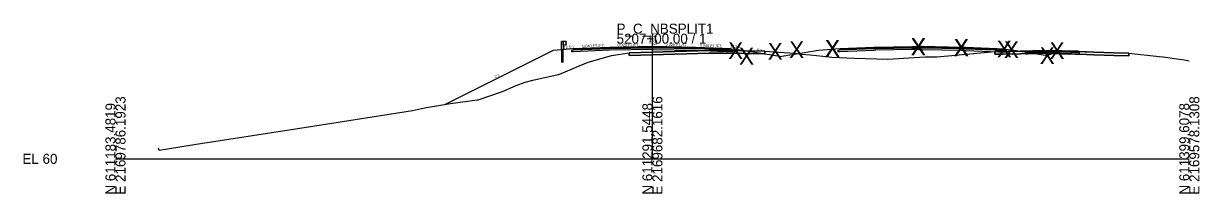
# Model space of a CAD drawing. Extents: x -26 to 1303, y -3010 to 12038.
# Drawn here: x 974.3 to 1302.8, y 4490.3 to 4537.8 of the extents above; entities that cross this region are included whole.
import ezdxf

# ---------------------------------------------------------------- set-up
doc = ezdxf.new("R2010")
doc.units = 0
for name, color, linetype in [('RD_GPK_XS_Cell', 7, 'Continuous'), ('RD_GPK_XS_Text_Node', 7, 'Continuous'), ('RD_PD_Final_TrvlWay', 7, 'Continuous'), ('RD_XS_Base', 7, 'Continuous'), ('RD_XS_ExGround', 7, 'Continuous'), ('RD_XS_ExPaveRet', 7, 'Continuous'), ('RD_XS_GR', 7, 'Continuous'), ('RD_XS_Greenside', 7, 'Continuous'), ('RD_XS_Pave', 7, 'Continuous'), ('RD_XS_PaveOvlay_CP', 7, 'Continuous'), ('RD_XS_TieSlope', 7, 'Continuous'), ('RD_XS_TX_Elev_EX', 7, 'Continuous'), ('RD_XS_TX_Elev_PR', 7, 'Continuous'), ('RD_XS_TX_ShdSlope', 7, 'Continuous'), ('RD_XS_TX_Slope', 7, 'Continuous')]:
    doc.layers.add(name, color=color, linetype=linetype)

msp = doc.modelspace()

# ---------------------------------------------------------------- linework, layer by layer
at = {"layer": 'RD_GPK_XS_Cell'}
for p, q in [((1150, 4500), (1150, 4535)), ((1000, 4500), (1150, 4500)), ((1150, 4500), (1300, 4500))]:
    msp.add_line(p, q, dxfattribs=at)
at = {"layer": 'RD_PD_Final_TrvlWay'}
for p, q in [((1125.11, 4530.53), (1124.61, 4530.49)), ((1124.61, 4530.49), (1124.61, 4526.92)), ((1125.11, 4526.92), (1125.11, 4530.53))]:
    msp.add_line(p, q, dxfattribs=at)
at = {"layer": 'RD_XS_Base'}
for p, q in [((1128, 4530.44), (1138, 4530.84)), ((1138, 4530.84), (1150, 4531.08)), ((1138, 4530.84), (1138, 4530.84)), ((1150, 4530.58), (1138, 4530.34)), ((1150, 4531.08), (1150, 4531.24)), ((1150, 4531.24), (1150, 4530.58)), ((1150, 4531.08), (1150, 4530.58)), ((1162, 4530.84), (1150, 4531.08)), ((1150, 4531.08), (1150, 4531.08)), ((1150, 4530.58), (1150, 4530.58)), ((1150, 4530.58), (1150, 4530.58)), ((1150, 4530.58), (1162, 4530.34)), ((1172, 4530.44), (1162, 4530.84)), ((1164, 4530.76), (1164, 4530.76)), ((1202.37, 4530.44), (1211.84, 4530.82)), ((1211.84, 4530.82), (1212.38, 4530.84)), ((1212.38, 4530.84), (1222.49, 4531.05)), ((1222.49, 4530.55), (1212.38, 4530.34)), ((1222.49, 4531.05), (1224.38, 4531.08)), ((1224.38, 4530.58), (1222.49, 4530.55)), ((1224.38, 4531.23), (1224.38, 4531.24)), ((1224.38, 4531.24), (1224.38, 4531.19)), ((1224.38, 4531.08), (1224.38, 4531.23)), ((1224.38, 4531.19), (1224.38, 4530.58)), ((1224.38, 4531.08), (1224.38, 4531.04)), ((1224.38, 4531.08), (1224.38, 4531.08)), ((1225.36, 4531.06), (1224.38, 4531.08)), ((1224.38, 4531.08), (1224.38, 4531.08)), ((1224.38, 4531.04), (1224.38, 4530.58)), ((1224.38, 4530.58), (1225.36, 4530.56)), ((1236.38, 4530.84), (1225.36, 4531.06)), ((1225.36, 4530.56), (1236.38, 4530.34)), ((1237.52, 4530.8), (1236.38, 4530.84)), ((1248.38, 4530.37), (1237.52, 4530.8)), ((1127.5, 4530.42), (1128, 4530.44)), ((1127.5, 4529.92), (1127.5, 4530.42)), ((1127.5, 4530.42), (1127.5, 4530.42)), ((1128, 4529.94), (1127.5, 4529.92)), ((1127.5, 4529.92), (1127.5, 4529.92)), ((1127.5, 4529.92), (1127.5, 4529.92)), ((1128, 4530.44), (1128, 4530.44)), ((1138, 4530.34), (1128, 4529.94)), ((1128, 4529.94), (1128, 4529.94)), ((1138, 4530.34), (1138, 4530.34)), ((1162, 4530.34), (1172.5, 4529.92)), ((1164, 4530.26), (1164, 4530.26)), ((1172.5, 4530.42), (1172, 4530.44)), ((1172, 4530.44), (1172, 4530.44)), ((1172.5, 4529.92), (1172.5, 4530.42)), ((1172.5, 4530.42), (1172.5, 4530.42)), ((1172.5, 4529.92), (1172.5, 4529.92)), ((1172.5, 4529.92), (1172.5, 4529.92)), ((1201.87, 4530.42), (1202.35, 4530.44)), ((1201.87, 4530.4), (1201.87, 4530.42)), ((1201.87, 4529.92), (1201.87, 4530.4)), ((1202.35, 4529.94), (1201.87, 4529.92)), ((1202.35, 4530.44), (1202.37, 4530.44)), ((1202.37, 4529.94), (1202.35, 4529.94)), ((1211.84, 4530.32), (1202.37, 4529.94)), ((1212.38, 4530.34), (1211.84, 4530.32)), ((1236.38, 4530.34), (1237.57, 4530.3)), ((1237.57, 4530.3), (1248.88, 4529.85)), ((1248.43, 4530.36), (1248.38, 4530.37)), ((1248.88, 4530.35), (1248.43, 4530.36)), ((1248.88, 4530.29), (1248.88, 4530.35)), ((1248.88, 4529.85), (1248.88, 4530.29)), ((1254.31, 4529.77), (1254.81, 4529.78)), ((1254.31, 4529.27), (1254.31, 4529.77)), ((1254.81, 4529.28), (1254.31, 4529.27)), ((1254.81, 4529.78), (1256.81, 4529.82)), ((1256.81, 4529.32), (1254.81, 4529.28)), ((1256.81, 4529.82), (1261.81, 4529.92)), ((1261.81, 4529.42), (1256.81, 4529.32)), ((1261.81, 4530), (1261.81, 4530.08)), ((1261.81, 4530.08), (1261.81, 4529.74)), ((1261.81, 4529.92), (1261.81, 4530)), ((1264.26, 4529.87), (1261.81, 4529.92)), ((1261.81, 4529.92), (1261.81, 4529.42)), ((1261.81, 4529.74), (1261.81, 4529.42)), ((1261.81, 4529.42), (1264.26, 4529.37)), ((1266.82, 4529.82), (1264.26, 4529.87)), ((1264.26, 4529.37), (1266.82, 4529.32)), ((1267.82, 4529.8), (1266.82, 4529.82)), ((1266.82, 4529.32), (1268.07, 4529.29)), ((1268.82, 4529.78), (1267.82, 4529.8)), ((1268.07, 4529.29), (1269.32, 4529.27)), ((1269.07, 4529.77), (1268.82, 4529.78)), ((1269.32, 4529.77), (1269.07, 4529.77)), ((1269.32, 4529.52), (1269.32, 4529.77)), ((1269.32, 4529.27), (1269.32, 4529.52))]:
    msp.add_line(p, q, dxfattribs=at)
at = {"layer": 'RD_XS_ExGround'}
msp.add_lwpolyline([(1011.97, 4503.1), (1012.12, 4502.48), (1012.18, 4502.44), (1024.34, 4504.4), (1026.29, 4504.7), (1055.68, 4509.24), (1082.98, 4513.47), (1086.32, 4514.23), (1093.59, 4515.45), (1101.02, 4516.46), (1101.14, 4516.48), (1101.17, 4516.48), (1101.21, 4516.49), (1101.29, 4516.52), (1108.12, 4518.87), (1111.98, 4520.51), (1114.42, 4521.44), (1116.64, 4521.98), (1123.69, 4523.57), (1123.84, 4523.61), (1128.06, 4525.36), (1128.7, 4525.63), (1132.04, 4527.01), (1135.67, 4528.07), (1138.57, 4528.94), (1143.47, 4529.67), (1162.67, 4530.23), (1165.84, 4530.33), (1169.95, 4530.27), (1181.38, 4530.13), (1185.22, 4529.83), (1189.9, 4529.5), (1191.52, 4529.28), (1194.1, 4529.07), (1199.36, 4528.5), (1200.11, 4528.39), (1206.38, 4528.18), (1215.73, 4527.88), (1223.11, 4528.32), (1226.32, 4528.5), (1227.4, 4528.53), (1229.46, 4528.56), (1234.72, 4528.98), (1245.7, 4529.99), (1252.86, 4530.14), (1260.67, 4530.33), (1273.28, 4529.87), (1283.1, 4529.51), (1291.6, 4528.6), (1292.7, 4528.5), (1296.49, 4527.95), (1298.65, 4527.65), (1300, 4527.42)], dxfattribs=at)
at = {"layer": 'RD_XS_ExPaveRet'}
for p, q in [((1162.67, 4530.23), (1143.47, 4529.67)), ((1256.28, 4530.22), (1252.86, 4530.14))]:
    msp.add_line(p, q, dxfattribs=at)
for points in [[(1181.38, 4530.13), (1181.38, 4529.38), (1181.38, 4529.38), (1181.38, 4529.38), (1181.38, 4529.38), (1169.95, 4529.52), (1169.95, 4529.52), (1165.84, 4529.58), (1162.67, 4529.48), (1162.67, 4529.48), (1143.47, 4528.92), (1143.47, 4528.92), (1143.47, 4528.92), (1143.47, 4529.67), (1143.47, 4529.67), (1162.67, 4530.23), (1162.67, 4530.23), (1165.84, 4530.33), (1169.95, 4530.27), (1169.95, 4530.27), (1181.38, 4530.13), (1181.38, 4530.13), (1181.38, 4530.13)], [(1143.47, 4529.67), (1143.47, 4528.92), (1162.67, 4529.48), (1165.84, 4529.58), (1169.95, 4529.52), (1181.38, 4529.38), (1181.38, 4529.38), (1181.38, 4530.13), (1181.38, 4530.13), (1169.95, 4530.27), (1165.84, 4530.33), (1162.67, 4530.23)], [(1283.1, 4529.51), (1283.1, 4529.14), (1283.1, 4528.76), (1283.1, 4528.76), (1278.97, 4528.91), (1273.28, 4529.12), (1267.18, 4529.34), (1260.67, 4529.58), (1256.28, 4529.47), (1252.86, 4529.39), (1247.99, 4529.29), (1245.7, 4529.24), (1245.7, 4529.72), (1245.7, 4529.99), (1247.99, 4530.04), (1252.86, 4530.14), (1256.28, 4530.22), (1260.67, 4530.33), (1267.18, 4530.09), (1273.28, 4529.87), (1278.97, 4529.66), (1283.1, 4529.51), (1283.1, 4529.51)], [(1252.86, 4530.14), (1247.99, 4530.04), (1245.7, 4529.99)], [(1245.7, 4529.99), (1245.7, 4529.72), (1245.7, 4529.24), (1247.99, 4529.29), (1252.86, 4529.39), (1256.28, 4529.47), (1260.67, 4529.58), (1267.18, 4529.34), (1273.28, 4529.12), (1278.97, 4528.91), (1283.1, 4528.76), (1283.1, 4529.14), (1283.1, 4529.51), (1278.97, 4529.66)], [(1267.18, 4530.09), (1260.67, 4530.33), (1256.28, 4530.22)], [(1278.97, 4529.66), (1273.28, 4529.87), (1267.18, 4530.09)]]:
    msp.add_lwpolyline(points, dxfattribs=at)
at = {"layer": 'RD_XS_GR'}
for points in [[(1125.11, 4532.92), (1125.11, 4530.53), (1124.61, 4530.49), (1124.61, 4532.92), (1124.86, 4532.92), (1125.11, 4532.92)], [(1125.77, 4532.92), (1125.77, 4531.76), (1125.11, 4531.76), (1125.11, 4532.92), (1125.77, 4532.92)], [(1126.04, 4532.63), (1125.77, 4532.92), (1125.77, 4531.76), (1125.77, 4531.76), (1125.77, 4531.76), (1126.04, 4532.05), (1126.04, 4532.05), (1125.77, 4532.34), (1125.77, 4532.34), (1126.04, 4532.63), (1126.04, 4532.63)]]:
    msp.add_lwpolyline(points, dxfattribs=at)
at = {"layer": 'RD_XS_Greenside'}
for p, q in [((1174, 4530.6), (1186.14, 4528.58)), ((1250.38, 4530.52), (1260.38, 4528.86)), ((1122.29, 4530.3), (1092.09, 4515.2)), ((1196.37, 4530.28), (1186.14, 4528.58)), ((1260.38, 4528.86), (1263.14, 4530.24))]:
    msp.add_line(p, q, dxfattribs=at)
at = {"layer": 'RD_XS_Pave'}
for p, q in [((1138, 4531.16), (1128, 4530.76)), ((1138, 4531), (1128, 4530.6)), ((1128, 4530.6), (1138, 4531)), ((1128, 4530.44), (1138, 4530.84)), ((1128, 4530.76), (1128, 4530.76)), ((1128, 4530.76), (1128, 4530.6)), ((1128, 4530.6), (1128, 4530.6)), ((1128, 4530.6), (1128, 4530.44)), ((1128, 4530.6), (1128, 4530.6)), ((1128, 4530.6), (1128, 4530.6)), ((1150, 4531.4), (1138, 4531.16)), ((1150, 4531.24), (1138, 4531)), ((1138, 4531), (1150, 4531.24)), ((1138, 4531.16), (1138, 4531.16)), ((1138, 4530.84), (1150, 4531.08)), ((1138, 4531), (1138, 4531)), ((1138, 4531), (1138, 4531)), ((1138, 4530.84), (1138, 4530.84)), ((1162, 4531.16), (1150, 4531.4)), ((1150, 4531.08), (1150, 4531.24)), ((1150, 4531.24), (1162, 4531)), ((1162, 4531), (1150, 4531.24)), ((1150, 4531.24), (1150, 4531.08)), ((1150, 4531.08), (1150, 4531.08)), ((1150, 4531.08), (1150, 4531.08)), ((1150, 4531.08), (1162, 4530.84)), ((1172, 4530.76), (1162, 4531.16)), ((1162, 4531), (1172, 4530.6)), ((1172, 4530.6), (1162, 4531)), ((1162, 4530.84), (1172, 4530.44)), ((1164, 4531.08), (1164, 4531.08)), ((1164, 4530.92), (1164, 4530.92)), ((1164, 4530.92), (1164, 4530.92)), ((1164, 4530.76), (1164, 4530.76)), ((1172, 4530.6), (1172, 4530.76)), ((1172, 4530.76), (1172, 4530.76)), ((1172, 4530.6), (1172, 4530.6)), ((1172, 4530.6), (1172, 4530.6)), ((1172, 4530.44), (1172, 4530.6)), ((1172, 4530.6), (1172, 4530.6)), ((1211.84, 4531.14), (1202.37, 4530.76)), ((1211.84, 4530.98), (1202.37, 4530.6)), ((1202.37, 4530.6), (1211.84, 4530.98)), ((1202.37, 4530.44), (1211.84, 4530.82)), ((1202.37, 4530.76), (1202.37, 4530.75)), ((1202.37, 4530.75), (1202.37, 4530.6)), ((1202.37, 4530.6), (1202.37, 4530.6)), ((1202.37, 4530.6), (1202.37, 4530.44)), ((1212.38, 4531.16), (1211.84, 4531.14)), ((1212.38, 4531), (1211.84, 4530.98)), ((1211.84, 4530.98), (1212.38, 4531)), ((1211.84, 4530.82), (1212.38, 4530.84)), ((1222.49, 4531.36), (1212.38, 4531.16)), ((1222.49, 4531.21), (1212.38, 4531)), ((1212.38, 4531), (1222.49, 4531.21)), ((1212.38, 4530.84), (1222.49, 4531.05)), ((1224.38, 4531.4), (1222.49, 4531.36)), ((1224.38, 4531.24), (1222.49, 4531.21)), ((1222.49, 4531.21), (1224.38, 4531.24)), ((1222.49, 4531.05), (1224.38, 4531.08)), ((1225.36, 4531.38), (1224.38, 4531.4)), ((1224.38, 4531.23), (1224.38, 4531.24)), ((1224.38, 4531.24), (1225.36, 4531.22)), ((1225.36, 4531.22), (1224.38, 4531.24)), ((1224.38, 4531.24), (1224.38, 4531.24)), ((1224.38, 4531.24), (1224.38, 4531.24)), ((1224.38, 4531.24), (1224.38, 4531.23)), ((1224.38, 4531.08), (1224.38, 4531.23)), ((1224.38, 4531.23), (1224.38, 4531.08)), ((1224.38, 4531.08), (1224.38, 4531.08)), ((1224.38, 4531.08), (1224.38, 4531.08)), ((1224.38, 4531.08), (1225.36, 4531.06)), ((1236.38, 4531.16), (1225.36, 4531.38)), ((1225.36, 4531.22), (1236.38, 4531)), ((1236.38, 4531), (1225.36, 4531.22)), ((1225.36, 4531.06), (1236.38, 4530.84)), ((1237.52, 4531.12), (1236.38, 4531.16)), ((1236.38, 4531), (1237.52, 4530.96)), ((1237.52, 4530.96), (1236.38, 4531)), ((1236.38, 4530.84), (1237.52, 4530.8)), ((1248.38, 4530.68), (1237.52, 4531.12)), ((1237.52, 4530.96), (1248.38, 4530.52)), ((1248.38, 4530.52), (1237.52, 4530.96)), ((1237.52, 4530.8), (1248.38, 4530.37)), ((1248.38, 4530.67), (1248.38, 4530.68)), ((1248.38, 4530.52), (1248.38, 4530.67)), ((1248.38, 4530.51), (1248.38, 4530.52)), ((1248.38, 4530.37), (1248.38, 4530.51)), ((1128, 4530.44), (1128, 4530.44)), ((1128, 4530.44), (1128, 4530.44)), ((1172, 4530.44), (1172, 4530.44)), ((1172, 4530.44), (1172, 4530.44)), ((1255.87, 4530.12), (1254.81, 4530.1)), ((1254.81, 4530.1), (1254.81, 4530.02)), ((1254.81, 4530.02), (1254.81, 4529.94)), ((1256.81, 4529.98), (1254.81, 4529.94)), ((1254.81, 4529.94), (1255.87, 4529.96)), ((1254.81, 4529.94), (1254.81, 4529.78)), ((1254.81, 4529.78), (1256.81, 4529.82)), ((1256.81, 4530.14), (1255.87, 4530.12)), ((1255.87, 4529.96), (1256.81, 4529.98)), ((1259.21, 4530.18), (1256.81, 4530.14)), ((1261.81, 4530.08), (1256.81, 4529.98)), ((1256.81, 4529.98), (1259.21, 4530.03)), ((1256.81, 4529.82), (1261.81, 4529.92)), ((1261.81, 4530.24), (1259.21, 4530.18)), ((1259.21, 4530.03), (1261.81, 4530.08)), ((1264.26, 4530.19), (1261.81, 4530.24)), ((1261.81, 4530.08), (1264.26, 4530.03)), ((1266.82, 4529.98), (1261.81, 4530.08)), ((1261.81, 4530.08), (1261.81, 4529.92)), ((1261.81, 4529.92), (1261.81, 4530.08)), ((1261.81, 4529.92), (1266.82, 4529.82)), ((1266.82, 4530.14), (1264.26, 4530.19)), ((1264.26, 4530.03), (1266.82, 4529.98)), ((1267.82, 4530.12), (1266.82, 4530.14)), ((1266.82, 4529.98), (1267.82, 4529.96)), ((1268.82, 4529.94), (1266.82, 4529.98)), ((1266.82, 4529.82), (1268.82, 4529.78)), ((1268.82, 4530.1), (1267.82, 4530.12)), ((1267.82, 4529.96), (1268.82, 4529.94)), ((1268.82, 4530.02), (1268.82, 4530.1)), ((1268.82, 4529.94), (1268.82, 4530.02)), ((1268.82, 4529.78), (1268.82, 4529.94))]:
    msp.add_line(p, q, dxfattribs=at)
at = {"layer": 'RD_XS_PaveOvlay_CP'}
for p, q in [((1128, 4530.76), (1138, 4531.16)), ((1138, 4531.16), (1150, 4531.4)), ((1150, 4531.4), (1162, 4531.16)), ((1162, 4531.16), (1172, 4530.76)), ((1211.84, 4531.14), (1202.37, 4530.76)), ((1212.38, 4531.16), (1211.84, 4531.14)), ((1222.49, 4531.36), (1212.38, 4531.16)), ((1224.38, 4531.4), (1222.49, 4531.36)), ((1225.36, 4531.38), (1224.38, 4531.4)), ((1236.38, 4531.16), (1225.36, 4531.38)), ((1237.52, 4531.12), (1236.38, 4531.16)), ((1248.38, 4530.68), (1237.52, 4531.12)), ((1254.81, 4530.1), (1256.81, 4530.14)), ((1256.81, 4530.14), (1261.81, 4530.24)), ((1261.81, 4530.24), (1266.82, 4530.14)), ((1266.82, 4530.14), (1268.82, 4530.1))]:
    msp.add_line(p, q, dxfattribs=at)
at = {"layer": 'RD_XS_TieSlope'}
for p, q in [((1128, 4530.76), (1122.29, 4530.3)), ((1172, 4530.76), (1174, 4530.6)), ((1202.37, 4530.76), (1196.37, 4530.28)), ((1248.38, 4530.68), (1250.38, 4530.52))]:
    msp.add_line(p, q, dxfattribs=at)

# ---------------------------------------------------------------- texts
at = {"layer": 'RD_GPK_XS_Cell'}
for s, p in [('P_C_NBSPLIT1', (1140, 4535)), ('5207+00.00 / 1', (1140, 4532.2)), ('EL 60', (974, 4498.6))]:
    msp.add_text(s, height=2.8, dxfattribs=at).set_placement(p)
for s, p in [('N 611183.4819', (1000, 4490)), ('E 2169786.1923', (1002.8, 4490)), ('N 611291.5448', (1150, 4490)), ('E 2169682.1616', (1152.8, 4490)), ('N 611399.6078', (1300, 4490)), ('E 2169578.1308', (1302.8, 4490))]:
    msp.add_text(s, height=2.8, rotation=90, dxfattribs=at).set_placement(p)
at = {"layer": 'RD_GPK_XS_Text_Node'}
for p in [(1171.16, 4527.89), (1174.21, 4526.36), (1182.21, 4527.7), (1188.21, 4528.18), (1198.21, 4528.58), (1198.21, 4528.42), (1222.21, 4529.06), (1222.21, 4528.9), (1234.21, 4528.82), (1234.21, 4528.66), (1246.21, 4528.34), (1248.21, 4528.18), (1258.21, 4526.51), (1260.97, 4527.89)]:
    msp.add_text('X', height=4.69, dxfattribs=at).set_placement(p)
at = {"layer": 'RD_XS_TX_Elev_EX'}
msp.add_text('89.86', height=0.6, rotation=90, dxfattribs=at).set_placement((1149.66, 4532.21))
at = {"layer": 'RD_XS_TX_Elev_PR'}
msp.add_text('91.40', height=1, rotation=90, dxfattribs=at).set_placement((1151.25, 4531.79))
at = {"layer": 'RD_XS_TX_ShdSlope'}
for rotation, p in [(4.5739, (1125.26, 4530.73)), (355.4261, (1171.69, 4531.2))]:
    msp.add_text('12.5:1', height=0.75, rotation=rotation, dxfattribs=at).set_placement(p)
at = {"layer": 'RD_XS_TX_Slope'}
for s, rotation, p in [('0.040 FT./FT.', 2.2906, (1130.45, 4531.1)), ('0.020 FT./FT.', 1.1458, (1140.25, 4531.46)), ('0.020 FT./FT.', 358.8542, (1153.7, 4531.58)), ('0.040 FT./FT.', 357.7094, (1163.26, 4531.37)), ('6:1', 350.5377, (1179.13, 4530.17)), ('2:1', 26.5651, (1106.13, 4522.57))]:
    msp.add_text(s, height=0.75, rotation=rotation, dxfattribs=at).set_placement(p)

doc.saveas('drawing.dxf')
